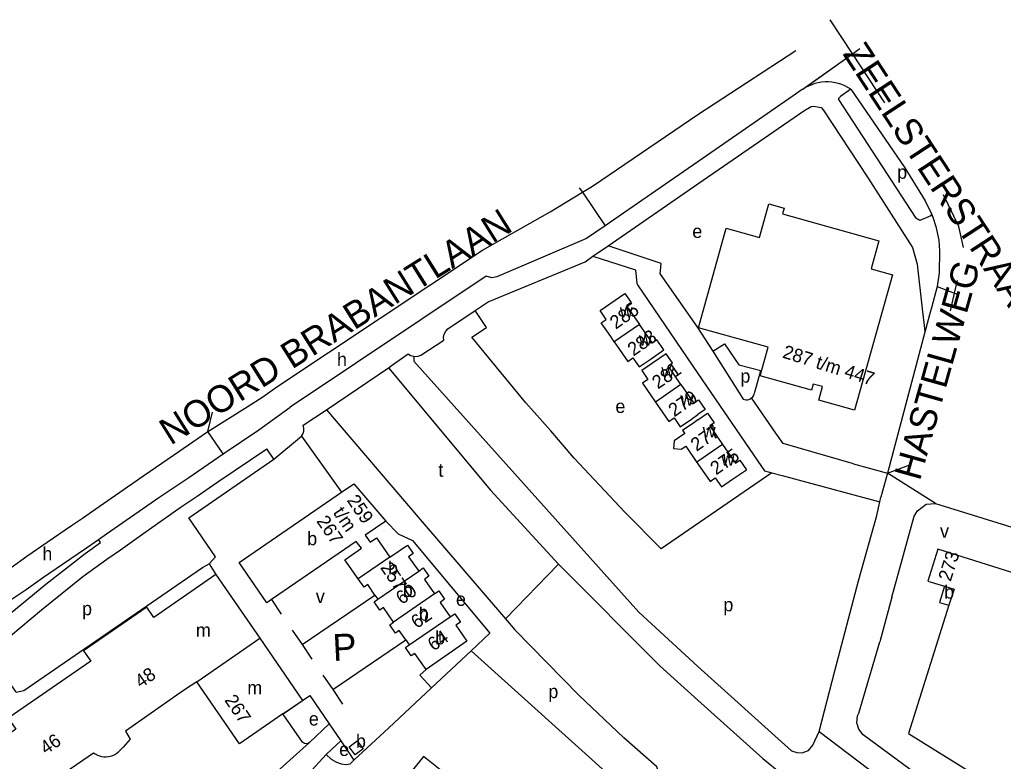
# Model space of a CAD drawing. Extents: x 157699 to 159683, y 381451 to 383293.
# Drawn here: x 157847.3 to 158141.2, y 383071.8 to 383293.3 of the extents above; entities that cross this region are included whole.
import ezdxf

# ---------------------------------------------------------------- set-up
doc = ezdxf.new("R2010")
doc.units = 0
for name, color, linetype in [('BLT_Basislijn', 7, 'Continuous'), ('BLT_Bebouwing', 7, 'Continuous'), ('BLT_Centroide', 7, 'Continuous'), ('BLT_Huisnummer', 7, 'Continuous'), ('BLT_Huisnummer_ tussenligend', 7, 'Continuous'), ('BLT_Huisnummer_reeks', 7, 'Continuous'), ('BLT_Huisnummer_zonder_bebouwing', 7, 'Continuous'), ('BLT_Onderverdeling_panden', 7, 'Continuous'), ('BLT_Plantopo', 7, 'Continuous'), ('BLT_Straatnaam_hoofdweg', 7, 'Continuous'), ('BLT_Tekst_parkeren', 7, 'Continuous'), ('BLT_Vlakafsluiter', 7, 'Continuous')]:
    doc.layers.add(name, color=color, linetype=linetype)

msp = doc.modelspace()

# ---------------------------------------------------------------- linework, layer by layer
at = {"layer": 'BLT_Basislijn'}
for p, q in [((158050, 383265.03), (158079.23, 383284.16)), ((158096.14, 383283.05), (158096.17, 383283)), ((158096.17, 383283), (158105.72, 383268.53)), ((158081.18, 383272.44), (158078.47, 383270.58)), ((158081.29, 383272.52), (158081.18, 383272.44)), ((158082.12, 383273.11), (158081.29, 383272.52)), ((158078.47, 383270.58), (158050, 383250.9)), ((158023.13, 383225.77), (158050, 383244.29)), ((158018.61, 383222.66), (158023.13, 383225.77)), ((158031.69, 383214.51), (158031.96, 383214.11)), ((158031.96, 383214.11), (158050, 383187.67)), ((158126.67, 383211.62), (158127.57, 383215.47)), ((158125.44, 383206.36), (158126.67, 383211.62)), ((158119.5, 383206.29), (158117.83, 383200.03)), ((158117.83, 383200.03), (158106.61, 383157.9)), ((158054.43, 383194.29), (158063.49, 383179.99)), ((157938.99, 383176.77), (157957.54, 383189.36)), ((157957.54, 383189.36), (157957.99, 383189.67)), ((158050, 383187.67), (158067.87, 383161.48)), ((158066.96, 383182.11), (158068.76, 383188.58)), ((157932.01, 383172.21), (157938.99, 383176.77)), ((157923.3, 383162.09), (157921.17, 383165.18)), ((158096.52, 383160.7), (158106.61, 383157.9)), ((158106.61, 383157.9), (158104.65, 383150.67)), ((158075.15, 383157.15), (158079.99, 383155.84)), ((158079.99, 383155.84), (158104.34, 383149.27)), ((158104.34, 383149.27), (158104.65, 383150.67)), ((157903.93, 383130.81), (157905.98, 383127.57)), ((157922.54, 383120.12), (157925.5, 383115.79)), ((157931.72, 383106.65), (157953.46, 383121.46)), ((158107.94, 383120.82), (158104.37, 383107.49)), ((157928.78, 383110.96), (157931.72, 383106.65)), ((157940.88, 383093.21), (157962.68, 383108.06)), ((157987.86, 383110.09), (157982.22, 383104.82)), ((157931.72, 383106.65), (157934.65, 383102.34)), ((157982.22, 383104.82), (157970.39, 383093.78)), ((158037.28, 383055.35), (157982.22, 383104.82)), ((158098.03, 383086.17), (158104.37, 383107.49)), ((158038.71, 383100.21), (158050, 383090.06)), ((157937.94, 383097.51), (157940.88, 383093.21)), ((157940.88, 383093.21), (157943.81, 383088.9)), ((157957.64, 383081.77), (157970.39, 383093.78)), ((157933.88, 383077.4), (157939.81, 383083.04)), ((157939.81, 383083.04), (157943.29, 383077.91)), ((157947.22, 383072.13), (157957.64, 383081.77)), ((158086.23, 383080.66), (158151.95, 383031.19)), ((157918.26, 383063.41), (157933.88, 383077.4)), ((157943.29, 383077.91), (157947.22, 383072.13))]:
    msp.add_line(p, q, dxfattribs=at)
for points in [[(158082.35, 383273.21), (158082.12, 383273.11)], [(158095.68, 383272.57), (158094.81, 383273.1), (158093.9, 383273.56), (158092.96, 383273.95), (158091.99, 383274.26), (158091, 383274.49), (158090, 383274.65), (158088.99, 383274.72), (158087.97, 383274.72), (158086.96, 383274.64), (158085.95, 383274.47), (158084.96, 383274.23), (158084, 383273.91), (158083.06, 383273.52), (158082.35, 383273.21)], [(158095.68, 383272.57), (158092.59, 383270.34), (158091.95, 383269.79), (158091.97, 383269.49), (158115.09, 383234.09)], [(158095.68, 383272.57), (158111.82, 383249.12), (158117.9, 383239.19), (158119.8, 383235.33)], [(158050, 383244.29), (158081.63, 383266.1), (158083.81, 383267.37), (158084.51, 383267.49), (158086.79, 383267.11), (158087.43, 383266.38), (158100.7, 383246.26), (158114.06, 383225.24), (158115.49, 383220.26), (158117.03, 383206.93)], [(158015.46, 383241.79), (158018.47, 383243.62), (158050, 383265.03)], [(158050, 383250.9), (158022.23, 383231.78)], [(157924.2, 383183.62), (157985.64, 383224.53), (158005.87, 383235.98), (158015.46, 383241.79)], [(158129.39, 383225.29), (158128, 383231.51), (158123.37, 383241.04)], [(158119.8, 383235.33), (158119.54, 383234.7), (158116.3, 383233.31), (158115.09, 383234.09)], [(158119.8, 383235.33), (158120.22, 383234.31), (158121.08, 383231.51), (158121.98, 383227.5), (158122.22, 383224.27)], [(158022.23, 383231.78), (158016.72, 383227.99), (157989.89, 383216.49), (157988.44, 383216.26), (157986.76, 383216.71)], [(158038.66, 383217.36), (158038.98, 383220.52), (158023.13, 383225.77)], [(157983.4, 383206.45), (157987.28, 383209.06), (158016.28, 383221.05), (158018.61, 383222.66)], [(158018.61, 383222.66), (158031.3, 383218.66), (158031.69, 383214.51)], [(158122.22, 383224.27), (158122.08, 383217.68), (158121.45, 383213.61)], [(157986.76, 383216.71), (157928.12, 383177.55)], [(158038.66, 383217.36), (158049.68, 383201.67), (158054.43, 383194.29)], [(158121.45, 383213.61), (158119.76, 383207.28), (158119.5, 383206.29)], [(157965.08, 383192.74), (157966.39, 383192.83), (157967.17, 383193.08), (157974.04, 383197.58), (157973.98, 383198.48), (157974.21, 383199.39), (157974.65, 383200.29), (157975.28, 383200.98), (157983.4, 383206.45)], [(158072.05, 383157.99), (158039.03, 383135.31), (158028.14, 383146.26), (158020.6, 383154.29), (158013.01, 383162.37), (158006.04, 383170.49), (157998.57, 383178.89), (157982.48, 383198.46), (157986.79, 383201.42), (157983.4, 383206.45)], [(158117.03, 383206.93), (158117.61, 383201.95)], [(158117.61, 383201.95), (158117.83, 383200.03)], [(158057.91, 383196.53), (158062.22, 383190.24), (158068.76, 383188.58)], [(157965.08, 383192.74), (157964.1, 383192.91), (157963.38, 383193.47), (157957.99, 383189.67)], [(157965.08, 383192.74), (157965.09, 383191.36), (158032.38, 383116.31), (158050, 383100.09), (158077.95, 383074.9), (158079.52, 383074.44), (158081.16, 383074.37), (158083.04, 383075.05), (158084.28, 383076.61), (158086.23, 383080.66)], [(157957.54, 383189.36), (157988.01, 383152.82), (158008.3, 383130.66)], [(157903.58, 383170.28), (157915.26, 383177.64), (157920.01, 383180.65), (157924.2, 383183.62)], [(158066.02, 383180.35), (158066.35, 383180.66), (158066.61, 383181.02), (158066.8, 383181.43), (158066.92, 383181.86), (158066.96, 383182.11)], [(158063.49, 383179.99), (158063.91, 383179.85), (158064.36, 383179.8), (158064.81, 383179.82), (158065.24, 383179.92), (158065.65, 383180.1), (158066.02, 383180.35)], [(158096.52, 383160.7), (158075.46, 383166.71), (158073.29, 383169.86), (158066.02, 383180.35)], [(157908.11, 383163.69), (157918.81, 383170.86), (157928.12, 383177.55)], [(157938.99, 383176.77), (157967.04, 383144.06), (157992.48, 383114.41)], [(157866.35, 383144.66), (157868.77, 383146.32), (157884.42, 383157.16), (157893.32, 383163.23), (157903.58, 383170.28)], [(157931.53, 383168.93), (157931.95, 383169.57), (157932.28, 383170.42), (157932.28, 383171.34), (157932.01, 383172.21)], [(157923.3, 383162.09), (157931.53, 383168.93)], [(157931.53, 383168.93), (157943.53, 383152.17)], [(157870.88, 383138.07), (157873.31, 383139.74), (157888.95, 383150.56), (157897.84, 383156.63), (157908.11, 383163.69)], [(157900.36, 383151.04), (157906.56, 383155.31), (157921.17, 383165.18)], [(157897.87, 383144.5), (157923.3, 383162.09)], [(158067.87, 383161.48), (158069.85, 383158.58), (158072.05, 383157.99)], [(158072.05, 383157.99), (158075.15, 383157.15)], [(157895.62, 383147.77), (157900.36, 383151.04)], [(158090.94, 383098.85), (158097.96, 383125.69), (158103.43, 383145.24), (158104.34, 383149.27)], [(158107.94, 383120.82), (158114.63, 383145.03), (158115.65, 383146.62), (158118.15, 383148.6), (158120.96, 383148.8)], [(158120.96, 383148.8), (158214.2, 383119.98), (158288.66, 383097.76)], [(157846.26, 383092.41), (157842.08, 383098.68), (157838.45, 383104.08), (157844.6, 383109.27), (157853.89, 383117.09), (157866.2, 383127.04), (157873.42, 383132.18), (157877.44, 383135.02), (157885.1, 383140.43), (157895.62, 383147.77)], [(157801.17, 383104.39), (157809.78, 383108.73), (157813.62, 383110.73), (157818.86, 383113.74), (157825.48, 383117.58), (157833.57, 383122.6), (157839.88, 383126.51), (157844.75, 383129.74), (157849.51, 383133.12), (157855.57, 383137.29), (157862.8, 383142.22), (157866.35, 383144.66)], [(157903.93, 383130.81), (157905.88, 383132.85), (157897.87, 383144.5)], [(157956.71, 383143.58), (157960.42, 383139.78), (157964.74, 383137.73), (157987.86, 383110.09)], [(157810.91, 383098.37), (157813.42, 383094.46), (157818.57, 383097.47), (157829.09, 383103.46), (157836.52, 383109.18), (157844.39, 383115.82), (157855.14, 383124.71), (157866.91, 383133.87), (157871.51, 383137.18), (157870.88, 383138.07)], [(157810.91, 383098.37), (157814.63, 383102.24), (157817.45, 383103.7), (157822.86, 383106.81), (157829.6, 383110.72), (157837.79, 383115.8), (157844.2, 383119.77), (157849.28, 383123.14), (157854.1, 383126.57), (157860.09, 383130.69), (157867.32, 383135.61), (157870.88, 383138.07)], [(157846.26, 383092.41), (157848.61, 383092.99), (157901.92, 383129.69), (157903.93, 383130.81)], [(158008.3, 383130.66), (158038.71, 383100.21)], [(157992.48, 383114.41), (157995.31, 383111.11), (158014.42, 383091.59)], [(157968.76, 383099.23), (157966.91, 383097.5), (157970.39, 383093.78)], [(158086.23, 383080.66), (158090.94, 383098.85)], [(157931.88, 383089.99), (157934.05, 383091.48), (157939.81, 383083.04)], [(158041.42, 383060.3), (158041.02, 383060.62), (158037.71, 383070.13), (158027.85, 383078.82), (158014.42, 383091.59)], [(158050, 383090.06), (158069.37, 383072.64), (158075.25, 383067.82)], [(157933.88, 383077.4), (157933.29, 383077.07), (157932.42, 383077.1), (157931.79, 383077.52), (157926.01, 383085.94)], [(158253.94, 382986.99), (158231.51, 382996.79), (158211.77, 383006.78), (158182.9, 383022.33), (158161.49, 383035.3), (158143.35, 383047.24), (158099.36, 383079.76), (158098.12, 383081.44), (158097.48, 383083.34), (158097.64, 383085.35), (158098.03, 383086.17)], [(157938.93, 383073.83), (157940.5, 383075.37), (157943.29, 383077.91)], [(157872.79, 383011.68), (157880.74, 383019.11), (157885.38, 383014.04), (157938.05, 383063.51), (157933.67, 383068.11), (157938.93, 383073.83)], [(157938.93, 383073.83), (157940.43, 383072.46), (157942.03, 383071.53), (157943.42, 383071.03), (157944.88, 383070.9), (157946.08, 383071.04), (157947.22, 383072.13)]]:
    msp.add_lwpolyline(points, dxfattribs=at)
at = {"layer": 'BLT_Bebouwing'}
for p, q in [((158020.79, 383206.45), (158028.17, 383211.53)), ((158054.43, 383194.29), (158057.91, 383196.53)), ((158049.68, 383161.11), (158050, 383160.64)), ((157905.98, 383127.57), (157919.08, 383108.56)), ((157953.46, 383121.46), (157954.31, 383120.2)), ((157919.08, 383108.56), (157931.88, 383089.99)), ((157962.68, 383108.06), (157963.72, 383106.55)), ((157896.84, 383093.31), (157894.33, 383091.57)), ((157900.22, 383095.59), (157896.84, 383093.31)), ((157913, 383077), (157900.22, 383095.59)), ((157926.01, 383085.94), (157931.88, 383089.99)), ((157967.98, 383073.26), (157953.94, 383055.93))]:
    msp.add_line(p, q, dxfattribs=at)
for points in [[(158028.17, 383211.53), (158030.04, 383208.83), (158028.67, 383207.89), (158032.52, 383202.31)], [(158024.98, 383197.11), (158023.92, 383198.65), (158021.08, 383202.77), (158022.61, 383203.82), (158020.79, 383206.45)], [(158024.98, 383197.11), (158029.03, 383191.23), (158030.58, 383192.3), (158032.43, 383189.62), (158035.69, 383191.86), (158039.8, 383194.7), (158037.75, 383197.68), (158036.37, 383196.73), (158032.52, 383202.31)], [(158044.9, 383184.37), (158041.06, 383189.93), (158042.4, 383190.85), (158040.52, 383193.56), (158036.41, 383190.73), (158033.19, 383188.5), (158034.99, 383185.89), (158033.39, 383184.79), (158037.29, 383179.12)], [(158044.9, 383184.37), (158048.73, 383178.81), (158050, 383179.69)], [(158037.29, 383179.12), (158041.3, 383173.31), (158042.87, 383174.4), (158044.72, 383171.72), (158048.06, 383174.02), (158050, 383175.36)], [(158050, 383179.69), (158050.15, 383179.8), (158052.18, 383176.86), (158050, 383175.36)], [(158050, 383173.8), (158052.86, 383175.77), (158054.83, 383172.92), (158053.52, 383172.02), (158057.38, 383166.42)], [(158050, 383173.8), (158048.74, 383172.93), (158045.42, 383170.64), (158046.05, 383169.74), (158042.92, 383167.58), (158042.74, 383165.25), (158045.02, 383165.06), (158046.33, 383165.96), (158049.68, 383161.11)], [(158057.38, 383166.42), (158061.24, 383160.83), (158062.52, 383161.71), (158064.48, 383158.88)], [(158050, 383160.64), (158053.63, 383155.38), (158055.19, 383156.45), (158057.04, 383153.75)], [(158057.04, 383153.75), (158060.36, 383156.04), (158064.48, 383158.88)], [(157943.53, 383152.17), (157947.22, 383154.7), (157956.71, 383143.58)], [(157922.54, 383120.12), (157921.16, 383119.17), (157912.92, 383131.2), (157943.53, 383152.17)], [(157956.71, 383143.58), (157950.6, 383139.33), (157952.05, 383137.23), (157953.93, 383138.52), (157957.91, 383132.76)], [(157948.51, 383126.28), (157944.52, 383132.03), (157949.46, 383135.44), (157947.92, 383137.5), (157937.1, 383130.09)], [(157957.91, 383132.76), (157963.18, 383136.39), (157964.88, 383133.89), (157963.56, 383132.93), (157966.55, 383128.64)], [(158281.7, 383074.95), (158271.45, 383078.18), (158274.25, 383087.09), (158242.72, 383097.03), (158239.9, 383088.08), (158219.93, 383094.38), (158222.75, 383103.34), (158191.23, 383113.25), (158188.4, 383104.29), (158168.45, 383110.6), (158171.26, 383119.55), (158121.71, 383135.15), (158118.72, 383125.66), (158123.64, 383124.12)], [(157937.1, 383130.09), (157922.54, 383120.12)], [(157966.55, 383128.64), (157967.88, 383129.55), (157969.59, 383127.06), (157968.25, 383126.1), (157971.25, 383121.81)], [(157905.98, 383127.57), (157887.46, 383114.78), (157885.36, 383117.83), (157866.43, 383104.81), (157868.56, 383101.72), (157843.85, 383084.66), (157846.14, 383081.36), (157836.87, 383074.96)], [(157953.46, 383121.46), (157951.33, 383124.58), (157950.22, 383123.78), (157948.51, 383126.28)], [(157971.25, 383121.81), (157972.59, 383122.73), (157974.29, 383120.22), (157972.95, 383119.27), (157975.95, 383114.98)], [(158123.64, 383124.12), (158122.14, 383119.29), (158124.98, 383118.41)], [(157959.02, 383113.37), (157956.03, 383117.71), (157954.92, 383116.94), (157953.21, 383119.44), (157954.31, 383120.2)], [(158124.98, 383118.41), (158112.95, 383080.12), (158136.6, 383065.4), (158135.98, 383063.43)], [(157975.95, 383114.98), (157977.31, 383115.88), (157979.01, 383113.39), (157977.66, 383112.47), (157980.98, 383107.65), (157968.76, 383099.23)], [(157962.68, 383108.06), (157960.73, 383110.89), (157959.63, 383110.11), (157957.92, 383112.6), (157959.02, 383113.37)], [(157968.76, 383099.23), (157965.45, 383104.04), (157964.34, 383103.28), (157962.63, 383105.78), (157963.72, 383106.55)], [(157894.33, 383091.57), (157878.98, 383080.84), (157880.3, 383078.4), (157878.29, 383076), (157877.32, 383075.16)], [(157926.39, 383086.2), (157931.88, 383089.99)], [(157926.01, 383085.94), (157913, 383077)], [(157836.87, 383074.96), (157847.92, 383058.94), (157851.08, 383061.12), (157852.92, 383058.41), (157859.51, 383062.96), (157857.36, 383066.06), (157869.39, 383074.29)], [(157869.39, 383074.29), (157869.91, 383074.01), (157870.25, 383073.82)], [(157870.25, 383073.82), (157870.5, 383073.68), (157871.14, 383073.43), (157871.79, 383073.26), (157872.46, 383073.16), (157873.14, 383073.15), (157873.82, 383073.21), (157874.48, 383073.36), (157875.13, 383073.58), (157875.74, 383073.87), (157876.31, 383074.24), (157876.84, 383074.66), (157877.32, 383075.16)], [(158014.48, 383035.58), (158000, 383047.32), (157971.87, 383070.11), (157968.86, 383072.55), (157967.98, 383073.26)]]:
    msp.add_lwpolyline(points, dxfattribs=at)
msp.add_lwpolyline([(157945.77, 383076.17), (157948.15, 383077.94), (157949.93, 383075.55), (157947.55, 383073.78)], close=True, dxfattribs=at)
at = {"layer": 'BLT_Onderverdeling_panden'}
for p, q in [((158032.52, 383202.31), (158024.98, 383197.11)), ((158044.9, 383184.37), (158037.29, 383179.12)), ((158057.38, 383166.42), (158050, 383161.33)), ((158050, 383161.33), (158049.68, 383161.11)), ((157957.91, 383132.76), (157948.51, 383126.28)), ((157954.31, 383120.2), (157966.55, 383128.64)), ((157971.25, 383121.81), (157959.02, 383113.37)), ((157963.72, 383106.55), (157975.95, 383114.98))]:
    msp.add_line(p, q, dxfattribs=at)
for points in [[(158123.64, 383124.12), (158126.52, 383123.22), (158124.98, 383118.41)], [(157900.22, 383095.59), (157919.08, 383108.56)]]:
    msp.add_lwpolyline(points, dxfattribs=at)
at = {"layer": 'BLT_Plantopo'}
msp.add_lwpolyline([(158071.21, 383238.34), (158075.74, 383237.07), (158075.26, 383235.36), (158104.06, 383227.28), (158101.72, 383218.92), (158108.15, 383217.12), (158096.81, 383176.72), (158086.08, 383179.73), (158087.2, 383183.72), (158084.42, 383184.5), (158083.9, 383182.66), (158068.62, 383186.95), (158071.01, 383195.47), (158050.12, 383201.33), (158058.46, 383231.05), (158068.39, 383228.27)], close=True, dxfattribs=at)
at = {"layer": 'BLT_Vlakafsluiter'}
for p, q in [((158089.38, 383293.33), (158096.14, 383283.05)), ((158098.33, 383284.66), (158096.14, 383283.05)), ((158098.36, 383284.62), (158096.17, 383283)), ((158096.14, 383283.05), (158082.12, 383273.11)), ((158096.17, 383283), (158082.35, 383273.21)), ((158014.54, 383243.15), (158015.46, 383241.79)), ((158015.46, 383241.79), (158022.23, 383231.78)), ((158121.45, 383213.61), (158126.67, 383211.62)), ((158126.67, 383211.62), (158127.91, 383211.15)), ((157903.58, 383170.28), (157904.93, 383176.05)), ((157908.11, 383163.69), (157903.58, 383170.28)), ((158106.61, 383157.9), (158113.3, 383160.36)), ((158120.96, 383148.8), (158106.61, 383157.9)), ((157992.48, 383114.41), (158008.3, 383130.66))]:
    msp.add_line(p, q, dxfattribs=at)

# ---------------------------------------------------------------- texts
at = {"layer": 'BLT_Centroide'}
for s, p in [('p', (158109.52, 383245.81)), ('e', (158048.31, 383228.13)), ('w', (158026.66, 383204.38)), ('w', (158032.35, 383195.97)), ('h', (157942.15, 383189.87)), ('w', (158039.05, 383186.44)), ('p', (158062.68, 383184.91)), ('e', (158025.33, 383175.86)), ('w', (158044.7, 383178.03)), ('w', (158051.41, 383168.55)), ('t', (157972.43, 383156.81)), ('w', (158057.01, 383160.09)), ('b', (157933.25, 383136.34)), ('v', (158122.34, 383138.59)), ('h', (157854.11, 383131.8)), ('b', (157957.39, 383127.54)), ('b', (157961.8, 383120.91)), ('b', (158123.57, 383120.4)), ('v', (157935.83, 383119.07)), ('e', (157977.7, 383118.24)), ('p', (158057.59, 383116.61)), ('p', (157865.97, 383115.44)), ('b', (157966.63, 383113.81)), ('m', (157899.99, 383109)), ('b', (157971.47, 383106.75)), ('m', (157915.35, 383091.78)), ('p', (158005.3, 383090.68)), ('e', (157933.74, 383082.5)), ('b', (157947.82, 383075.87)), ('e', (157942.8, 383073.4))]:
    msp.add_text(s, height=4, dxfattribs=at).set_placement(p)
at = {"layer": 'BLT_Huisnummer'}
for s, rotation, p in [('285', 34.5907, (158025.43, 383200.72)), ('283', 34.5864, (158030.71, 383192.69)), ('279', 34.5899, (158042.92, 383174.53)), ('275', 34.6016, (158055.43, 383157.18)), ('257', 304.4124, (157954.92, 383129.67)), ('60', 34.4124, (157961.49, 383118.47)), ('62', 34.4124, (157965.99, 383111.3)), ('64', 34.4124, (157970.98, 383104.6))]:
    msp.add_text(s, height=4, rotation=rotation, dxfattribs=at).set_placement(p)
at = {"layer": 'BLT_Huisnummer_ tussenligend'}
for s, rotation, p in [('281', 34.5912, (158038.03, 383182.83)), ('277', 34.5972, (158049.58, 383164.24))]:
    msp.add_text(s, height=4, rotation=rotation, dxfattribs=at).set_placement(p)
at = {"layer": 'BLT_Huisnummer_reeks'}
for s, rotation, p in [('259', 304.4127, (157944.95, 383149.75)), ('t/m', 304.4127, (157940.8, 383146.08)), ('267', 304.4127, (157935.87, 383143.54)), ('273', 72.5665, (158125.51, 383125.31)), ('48', 34.5834, (157883.5, 383093.5)), ('267', 304.2491, (157908.37, 383090.06)), ('46', 34.2491, (157855.17, 383073.68))]:
    msp.add_text(s, height=4, rotation=rotation, dxfattribs=at).set_placement(p)
at = {"layer": 'BLT_Huisnummer_zonder_bebouwing'}
msp.add_text('287 t/m 447', height=4, rotation=342.5665, dxfattribs=at).set_placement((158075.01, 383192.45))
at = {"layer": 'BLT_Straatnaam_hoofdweg'}
for s, rotation, p in [('ZEELSTERSTRAAT', 303.1944, (158093.09, 383283.13)), ('NOORD BRABANTLAAN', 32.0986, (157892.41, 383166.04)), ('HASTELWEG', 74.3482, (158116.3, 383155.34))]:
    msp.add_text(s, height=8, rotation=rotation, dxfattribs=at).set_placement(p)
at = {"layer": 'BLT_Tekst_parkeren'}
msp.add_text('P', height=8, rotation=2.8586, dxfattribs=at).set_placement((157941.04, 383101.75))

doc.saveas('drawing.dxf')
